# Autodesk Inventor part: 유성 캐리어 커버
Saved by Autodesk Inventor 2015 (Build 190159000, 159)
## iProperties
Created: 2026-05
Part Number: 유성 캐리어 커버
Material: 일반
Document SubType Name: Modeling
Designer: 104
Density: 1 g/cm^3
Appearance: 기본값
Author: 104
Author: jhkim
Creation Date: 2026-04-27
Sending System: Autodesk Inventor 2027
Preprocessor: ST-DEVELOPER v20.1
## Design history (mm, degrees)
node "유성 캐리어 커버1"
node "솔리드1"
node "기준1"
